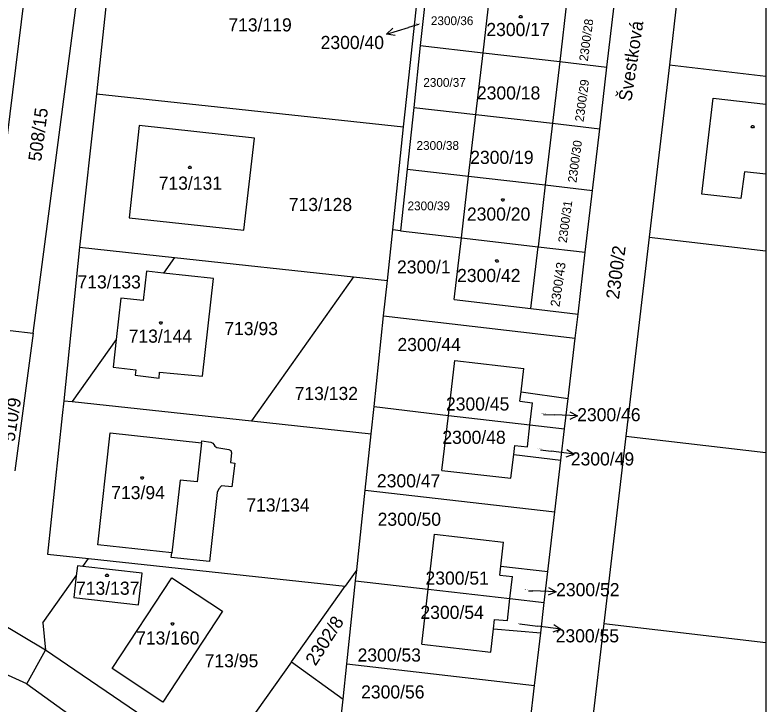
# Model space of a CAD drawing. Extents: x -639590 to -639298, y -1193269 to -1192863.
# Drawn here: x -639395.8 to -639298.4, y -1193033.8 to -1192944.4 of the extents above; entities that cross this region are included whole.
import ezdxf

# ---------------------------------------------------------------- set-up
doc = ezdxf.new("R2010")
doc.units = 0
for name, color, linetype in [('Vrstva 1', 7, 'Continuous'), ('Vrstva 2', 7, 'Continuous'), ('Vrstva 4', 7, 'Continuous'), ('Vrstva 5', 7, 'Continuous'), ('Vrstva 61', 7, 'Continuous'), ('Vrstva 7', 7, 'Continuous')]:
    doc.layers.add(name, color=color, linetype=linetype)

msp = doc.modelspace()

# ---------------------------------------------------------------- linework, layer by layer
at = {"layer": 'Vrstva 1'}
for p, q in [((-639383.03, -1192934.71), (-639385.21, -1192954.59)), ((-639393.89, -1192936.45), (-639396.82, -1192960.36)), ((-639393.41, -1192985.63), (-639387.1, -1192937.37)), ((-639345.16, -1192956.92), (-639343.26, -1192938.99)), ((-639309.56, -1192939.2), (-639310.92, -1192950.83)), ((-639342.35, -1192940.34), (-639343.21, -1192948.35)), ((-639335.07, -1192949.28), (-639334.13, -1192941.29)), ((-639324.19, -1192942.43), (-639325.13, -1192950.42)), ((-639319.01, -1192951.12), (-639318.07, -1192943.13)), ((-639343.21, -1192948.35), (-639344.07, -1192956.35)), ((-639343.21, -1192948.35), (-639335.07, -1192949.28)), ((-639336, -1192957.28), (-639335.07, -1192949.28)), ((-639335.07, -1192949.28), (-639325.13, -1192950.42)), ((-639325.13, -1192950.42), (-639326.07, -1192958.42)), ((-639325.13, -1192950.42), (-639319.01, -1192951.12)), ((-639310.92, -1192950.83), (-639313.54, -1192973.18)), ((-639310.92, -1192950.83), (-639298.391, -1192952.297)), ((-639319.94, -1192959.12), (-639319.01, -1192951.12)), ((-639385.21, -1192954.59), (-639387.39, -1192974.48)), ((-639385.21, -1192954.59), (-639345.37, -1192958.88)), ((-639306.71, -1192967.58), (-639305.24, -1192955.15)), ((-639305.24, -1192955.15), (-639298.391, -1192955.938)), ((-639344.07, -1192956.35), (-639344.93, -1192964.35)), ((-639344.07, -1192956.35), (-639336, -1192957.28)), ((-639345.37, -1192958.88), (-639345.16, -1192956.92)), ((-639336.94, -1192965.27), (-639336, -1192957.28)), ((-639336, -1192957.28), (-639326.07, -1192958.42)), ((-639379.65, -1192958.7), (-639380.96, -1192970.68)), ((-639364.71, -1192960.36), (-639379.65, -1192958.7)), ((-639326.07, -1192958.42), (-639327, -1192966.41)), ((-639326.07, -1192958.42), (-639319.94, -1192959.12)), ((-639346.65, -1192970.97), (-639345.37, -1192958.88)), ((-639320.88, -1192967.11), (-639319.94, -1192959.12)), ((-639366.1, -1192972.28), (-639364.71, -1192960.36)), ((-639344.93, -1192964.35), (-639345.79, -1192972.36)), ((-639344.93, -1192964.35), (-639336.94, -1192965.27)), ((-639337.88, -1192973.27), (-639336.94, -1192965.27)), ((-639336.94, -1192965.27), (-639327, -1192966.41)), ((-639301.16, -1192964.71), (-639301.64, -1192968.16)), ((-639298.391, -1192965.018), (-639301.16, -1192964.71)), ((-639327, -1192966.41), (-639327.94, -1192974.41)), ((-639327, -1192966.41), (-639320.88, -1192967.11)), ((-639321.82, -1192975.11), (-639320.88, -1192967.11)), ((-639301.64, -1192968.16), (-639306.71, -1192967.58)), ((-639380.96, -1192970.68), (-639366.1, -1192972.28)), ((-639346.79, -1192972.24), (-639346.65, -1192970.97)), ((-639347.48, -1192978.77), (-639346.79, -1192972.24)), ((-639345.79, -1192972.36), (-639346.79, -1192972.24)), ((-639345.79, -1192972.36), (-639337.88, -1192973.27)), ((-639338.82, -1192981.25), (-639337.88, -1192973.27)), ((-639337.88, -1192973.27), (-639327.94, -1192974.41)), ((-639313.54, -1192973.18), (-639316.56, -1192998.97)), ((-639313.54, -1192973.18), (-639298.391, -1192974.948)), ((-639328.88, -1192982.42), (-639327.94, -1192974.41)), ((-639327.94, -1192974.41), (-639321.82, -1192975.11)), ((-639387.39, -1192974.48), (-639389.43, -1192994.38)), ((-639387.39, -1192974.48), (-639375.09, -1192975.8)), ((-639322.76, -1192983.14), (-639321.82, -1192975.11)), ((-639375.09, -1192975.8), (-639376.52, -1192977.82)), ((-639375.09, -1192975.8), (-639351.85, -1192978.3)), ((-639378.73, -1192977.57), (-639379.13, -1192981.37)), ((-639376.52, -1192977.82), (-639378.73, -1192977.57)), ((-639370.03, -1192978.54), (-639376.52, -1192977.82)), ((-639351.85, -1192978.3), (-639365.1, -1192996.99)), ((-639351.85, -1192978.3), (-639347.48, -1192978.77)), ((-639371.45, -1192991.2), (-639370.03, -1192978.54)), ((-639347.97, -1192983.38), (-639347.48, -1192978.77)), ((-639382.05, -1192981.06), (-639382.64, -1192986.44)), ((-639379.13, -1192981.37), (-639382.05, -1192981.06)), ((-639338.82, -1192981.25), (-639328.88, -1192982.42)), ((-639328.88, -1192982.42), (-639322.76, -1192983.14)), ((-639323.13, -1192986.27), (-639322.76, -1192983.14)), ((-639349.21, -1192995.14), (-639347.97, -1192983.38)), ((-639347.97, -1192983.38), (-639323.13, -1192986.27)), ((-639396.4, -1192985.25), (-639393.41, -1192985.63)), ((-639393.41, -1192985.63), (-639395.79, -1193003.46)), ((-639382.64, -1192986.44), (-639388.35, -1192994.49)), ((-639382.64, -1192986.44), (-639383.03, -1192990.01)), ((-639324.04, -1192994.08), (-639323.13, -1192986.27)), ((-639383.03, -1192990.01), (-639380.1, -1192990.35)), ((-639339.57, -1192996.27), (-639338.74, -1192989.14)), ((-639338.74, -1192989.14), (-639329.8, -1192990.18)), ((-639380.1, -1192990.35), (-639380.16, -1192991.08)), ((-639377.07, -1192991.44), (-639377.01, -1192990.69)), ((-639377.01, -1192990.69), (-639371.45, -1192991.2)), ((-639330.15, -1192993.23), (-639329.8, -1192990.18)), ((-639380.16, -1192991.08), (-639377.07, -1192991.44)), ((-639330.29, -1192994.42), (-639330.15, -1192993.23)), ((-639330.15, -1192993.23), (-639324.04, -1192994.08)), ((-639389.43, -1192994.38), (-639389.63, -1192996.3)), ((-639389.43, -1192994.38), (-639388.35, -1192994.49)), ((-639388.35, -1192994.49), (-639365.1, -1192996.99)), ((-639330.29, -1192994.42), (-639328.66, -1192994.65)), ((-639328.99, -1192997.5), (-639328.66, -1192994.65)), ((-639324.5, -1192998.02), (-639324.04, -1192994.08)), ((-639349.58, -1192998.66), (-639349.21, -1192995.14)), ((-639349.21, -1192995.14), (-639339.57, -1192996.27)), ((-639389.63, -1192996.3), (-639391.56, -1193014.27)), ((-639340.4, -1193003.4), (-639339.57, -1192996.27)), ((-639339.57, -1192996.27), (-639328.99, -1192997.5)), ((-639365.1, -1192996.99), (-639349.58, -1192998.66)), ((-639329.33, -1193000.35), (-639328.99, -1192997.5)), ((-639328.99, -1192997.5), (-639324.5, -1192998.02)), ((-639385, -1193013.06), (-639383.4, -1192998.52)), ((-639383.4, -1192998.52), (-639371.56, -1192999.81)), ((-639350.36, -1193005.95), (-639349.58, -1192998.66)), ((-639324.98, -1193002.06), (-639324.5, -1192998.02)), ((-639371.56, -1192999.81), (-639371.54, -1192999.58)), ((-639371.54, -1192999.58), (-639370.37, -1192999.75)), ((-639316.56, -1192998.97), (-639319.4, -1193023.24)), ((-639316.56, -1192998.97), (-639298.391, -1193001.096)), ((-639370.37, -1192999.75), (-639370.12, -1192999.88)), ((-639370.12, -1192999.88), (-639369.99, -1193000.06)), ((-639369.99, -1193000.06), (-639369.86, -1193000.28)), ((-639369.86, -1193000.28), (-639369.57, -1193000.43)), ((-639369.57, -1193000.43), (-639368.03, -1193000.71)), ((-639368.03, -1193000.71), (-639367.76, -1193000.83)), ((-639331.1, -1193001.35), (-639330.97, -1193000.16)), ((-639330.97, -1193000.16), (-639329.33, -1193000.35)), ((-639367.71, -1193001.13), (-639367.82, -1193002.4)), ((-639367.76, -1193000.83), (-639367.71, -1193001.13)), ((-639331.46, -1193004.43), (-639331.1, -1193001.35)), ((-639331.1, -1193001.35), (-639324.98, -1193002.06)), ((-639367.82, -1193002.4), (-639367.25, -1193002.47)), ((-639367.25, -1193002.47), (-639367.65, -1193005.55)), ((-639325.76, -1193008.79), (-639324.98, -1193002.06)), ((-639340.4, -1193003.4), (-639331.46, -1193004.43)), ((-639368.97, -1193005.42), (-639369.34, -1193005.78)), ((-639367.65, -1193005.55), (-639368.97, -1193005.42)), ((-639369.53, -1193006.28), (-639370.56, -1193015.2)), ((-639369.34, -1193005.78), (-639369.53, -1193006.28)), ((-639351.45, -1193016.27), (-639350.36, -1193005.95)), ((-639350.36, -1193005.95), (-639325.76, -1193008.79)), ((-639326.66, -1193016.49), (-639325.76, -1193008.79)), ((-639342.18, -1193018.8), (-639341.36, -1193011.67)), ((-639341.36, -1193011.67), (-639332.41, -1193012.71)), ((-639375.43, -1193014.08), (-639385, -1193013.06)), ((-639332.76, -1193015.8), (-639332.41, -1193012.71)), ((-639391.56, -1193014.27), (-639386.24, -1193014.84)), ((-639375.49, -1193014.71), (-639375.43, -1193014.08)), ((-639386.95, -1193015.84), (-639386.24, -1193014.84)), ((-639386.24, -1193014.84), (-639352.97, -1193018.41)), ((-639370.56, -1193015.2), (-639375.49, -1193014.71)), ((-639387.67, -1193015.75), (-639387.82, -1193017.06)), ((-639386.95, -1193015.84), (-639387.67, -1193015.75)), ((-639379.28, -1193016.74), (-639386.95, -1193015.84)), ((-639351.45, -1193016.27), (-639352.97, -1193018.41)), ((-639351.6, -1193017.71), (-639351.45, -1193016.27)), ((-639332.9, -1193016.99), (-639332.76, -1193015.8)), ((-639332.76, -1193015.8), (-639326.66, -1193016.49)), ((-639392.15, -1193023.17), (-639387.82, -1193017.06)), ((-639387.82, -1193017.06), (-639388.13, -1193019.87)), ((-639379.76, -1193020.83), (-639379.28, -1193016.74)), ((-639332.9, -1193016.99), (-639331.26, -1193017.17)), ((-639331.59, -1193020.02), (-639331.26, -1193017.17)), ((-639327.14, -1193020.54), (-639326.66, -1193016.49)), ((-639383.17, -1193029.06), (-639375.42, -1193017.33)), ((-639375.42, -1193017.33), (-639368.86, -1193021.65)), ((-639352.74, -1193028.49), (-639351.6, -1193017.71)), ((-639351.6, -1193017.71), (-639342.18, -1193018.8)), ((-639359.93, -1193028.23), (-639352.97, -1193018.41)), ((-639342.99, -1193025.93), (-639342.18, -1193018.8)), ((-639342.18, -1193018.8), (-639331.59, -1193020.02)), ((-639388.13, -1193019.87), (-639379.76, -1193020.83)), ((-639331.92, -1193022.87), (-639331.59, -1193020.02)), ((-639331.59, -1193020.02), (-639327.14, -1193020.54)), ((-639391.81, -1193026.72), (-639401.32, -1193021.01)), ((-639327.6, -1193024.45), (-639327.14, -1193020.54)), ((-639368.86, -1193021.65), (-639376.61, -1193033.42)), ((-639333.72, -1193023.92), (-639333.58, -1193022.73)), ((-639333.58, -1193022.73), (-639331.92, -1193022.87)), ((-639392.15, -1193023.17), (-639391.81, -1193026.72)), ((-639334.07, -1193026.98), (-639333.72, -1193023.92)), ((-639333.72, -1193023.92), (-639327.6, -1193024.45)), ((-639319.4, -1193023.24), (-639322.6, -1193050.55)), ((-639319.4, -1193023.24), (-639298.391, -1193025.698)), ((-639328.4, -1193031.29), (-639327.6, -1193024.45)), ((-639342.99, -1193025.93), (-639334.07, -1193026.98)), ((-639394.21, -1193031.06), (-639391.81, -1193026.72)), ((-639388.01, -1193029.3), (-639391.81, -1193026.72)), ((-639359.93, -1193028.23), (-639369.56, -1193041.81)), ((-639359.93, -1193028.23), (-639353.23, -1193033.04)), ((-639353.23, -1193033.04), (-639352.74, -1193028.49)), ((-639352.74, -1193028.49), (-639328.4, -1193031.29)), ((-639394.21, -1193031.06), (-639398.1, -1193029.3)), ((-639369.56, -1193041.81), (-639388.01, -1193029.3)), ((-639376.61, -1193033.42), (-639383.17, -1193029.06)), ((-639394.21, -1193031.06), (-639377.41, -1193043.16)), ((-639329.3, -1193039.04), (-639328.4, -1193031.29)), ((-639353.99, -1193040.25), (-639353.23, -1193033.04))]:
    msp.add_line(p, q, dxfattribs=at)
at = {"layer": 'Vrstva 4'}
for p, q in [((-639371.56, -1192999.81), (-639372.13, -1193004.88)), ((-639374.33, -1193004.66), (-639375.43, -1193014.08)), ((-639372.13, -1193004.88), (-639374.33, -1193004.66))]:
    msp.add_line(p, q, dxfattribs=at)
at = {"layer": 'Vrstva 5'}
for points in [[(-639330.11, -1192944.46), (-639330.02, -1192944.61), (-639330.11, -1192944.76), (-639330.29, -1192944.76), (-639330.38, -1192944.61), (-639330.29, -1192944.46)], [(-639300.03, -1192958.72), (-639299.94, -1192958.87), (-639300.03, -1192959.02), (-639300.21, -1192959.02), (-639300.3, -1192958.87), (-639300.21, -1192958.72)], [(-639372.99, -1192963.99), (-639372.9, -1192964.14), (-639372.99, -1192964.29), (-639373.17, -1192964.29), (-639373.26, -1192964.14), (-639373.17, -1192963.99)], [(-639332.41, -1192968.2), (-639332.32, -1192968.35), (-639332.41, -1192968.5), (-639332.59, -1192968.5), (-639332.68, -1192968.35), (-639332.59, -1192968.2)], [(-639333.18, -1192976.11), (-639333.09, -1192976.26), (-639333.18, -1192976.41), (-639333.36, -1192976.41), (-639333.45, -1192976.26), (-639333.36, -1192976.11)], [(-639376.77, -1192984.13), (-639376.68, -1192984.28), (-639376.77, -1192984.43), (-639376.95, -1192984.43), (-639377.04, -1192984.28), (-639376.95, -1192984.13)], [(-639379.19, -1193004.22), (-639379.1, -1193004.37), (-639379.19, -1193004.52), (-639379.37, -1193004.52), (-639379.46, -1193004.37), (-639379.37, -1193004.22)], [(-639383.74, -1193016.87), (-639383.65, -1193017.02), (-639383.74, -1193017.17), (-639383.92, -1193017.17), (-639384.01, -1193017.02), (-639383.92, -1193016.87)], [(-639375.26, -1193023.15), (-639375.17, -1193023.3), (-639375.26, -1193023.45), (-639375.44, -1193023.45), (-639375.53, -1193023.3), (-639375.44, -1193023.15)]]:
    msp.add_lwpolyline(points, close=True, dxfattribs=at)
at = {"layer": 'Vrstva 61'}
msp.add_lwpolyline([(-639298.391, -1192863.27), (-639298.391, -1193268.77)], dxfattribs=at)
at = {"layer": 'Vrstva 7'}
for p, q in [((-639347.588, -1192946.869), (-639344.72, -1192945.99)), ((-639343.46, -1192945.61), (-639344.72, -1192945.99)), ((-639327.22, -1192996.16), (-639325.82, -1192996.22)), ((-639322.822, -1192996.335), (-639325.82, -1192996.22)), ((-639327.64, -1193000.73), (-639326.25, -1193000.91)), ((-639323.276, -1193001.306), (-639326.25, -1193000.91)), ((-639329.17, -1193019), (-639328.6, -1193019.02)), ((-639325.602, -1193019.126), (-639328.6, -1193019.02)), ((-639330.34, -1193023.28), (-639327.95, -1193023.59)), ((-639324.976, -1193023.983), (-639327.95, -1193023.59))]:
    msp.add_line(p, q, dxfattribs=at)
for points in [[(-639346.486, -1192947.054), (-639347.588, -1192946.869), (-639346.779, -1192946.098)], [(-639323.802, -1192995.797), (-639322.822, -1192996.335), (-639323.841, -1192996.796)], [(-639324.201, -1193000.678), (-639323.276, -1193001.306), (-639324.334, -1193001.67)], [(-639326.584, -1193018.591), (-639325.602, -1193019.126), (-639326.619, -1193019.59)], [(-639325.902, -1193023.356), (-639324.976, -1193023.983), (-639326.033, -1193024.348)]]:
    msp.add_lwpolyline(points, dxfattribs=at)

# ---------------------------------------------------------------- texts
at = {"layer": 'Vrstva 2'}
for s, height, p in [('713/119', 1.7, (-639368.095, -1192946.51)), ('2300/36', 1.14, (-639341.839, -1192945.69)), ('2300/40', 0.1, (-639343.757, -1192945.61)), ('2300/17', 1.7, (-639334.648, -1192947.11)), ('2300/37', 1.14, (-639342.822, -1192953.69)), ('2300/18', 1.7, (-639335.868, -1192955.33)), ('2300/38', 1.14, (-639343.702, -1192961.86)), ('2300/19', 1.7, (-639336.738, -1192963.68)), ('713/131', 1.7, (-639377.132, -1192967.02)), ('713/128', 1.7, (-639360.266, -1192969.79)), ('2300/39', 1.14, (-639344.869, -1192969.69)), ('2300/20', 1.7, (-639337.166, -1192971.03)), ('2300/1', 1.7, (-639346.233, -1192977.88)), ('2300/42', 1.7, (-639338.44, -1192978.99)), ('713/133', 1.7, (-639387.657, -1192979.82)), ('713/93', 1.7, (-639368.618, -1192985.87)), ('713/144', 1.7, (-639381.023, -1192986.85)), ('2300/44', 1.7, (-639346.173, -1192987.94)), ('713/132', 1.7, (-639359.503, -1192994.28)), ('2300/45', 1.7, (-639339.883, -1192995.64)), ('2300/46', 0.1, (-639327.496, -1192996.08)), ('2300/48', 1.7, (-639340.356, -1192999.96)), ('2300/49', 0.1, (-639327.996, -1193000.65)), ('2300/47', 1.7, (-639348.833, -1193005.6)), ('713/94', 1.7, (-639383.281, -1193007.13)), ('713/134', 1.7, (-639365.77, -1193008.73)), ('2300/50', 1.7, (-639348.743, -1193010.58)), ('2300/51', 1.7, (-639342.535, -1193018.21)), ('713/137', 1.7, (-639387.849, -1193019.52)), ('2300/52', 0.1, (-639329.746, -1193018.92)), ('2300/54', 1.7, (-639343.193, -1193022.65)), ('2300/55', 0.1, (-639330.656, -1193023.32)), ('713/160', 1.7, (-639380.059, -1193025.97)), ('2300/53', 1.7, (-639351.343, -1193028.18)), ('713/95', 1.7, (-639371.168, -1193028.92)), ('2300/56', 1.7, (-639350.883, -1193032.96))]:
    msp.add_text(s, height=height, dxfattribs=at).set_placement(p)
for s, height, rotation, p in [('2300/28', 1.14, 82.33404, (-639321.498, -1192950.423)), ('2300/29', 1.14, 82.33404, (-639322.046, -1192958.279)), ('508/15', 1.7, 82.50592, (-639392.371, -1192963.418)), ('2300/30', 1.14, 82.33404, (-639322.97, -1192966.166)), ('2300/31', 1.14, 82.33404, (-639324.226, -1192973.967)), ('2300/2', 1.7, 82.62051, (-639317.46, -1192981.285)), ('2300/43', 1.2, 81.87567, (-639325.166, -1192982.254)), ('510/9', 1.7, 81.13083, (-639395.827, -1192999.741)), ('2302/8', 1.7, 57.23848, (-639356.802, -1193028.84))]:
    msp.add_text(s, height=height, rotation=rotation, dxfattribs=at).set_placement(p)
at = {"layer": 'Vrstva 7'}
msp.add_text('Švestková', height=1.7, rotation=81.36001, dxfattribs=at).set_placement((-639315.844, -1192955.645))
for s, p in [('2300/40', (-639356.133, -1192948.79)), ('2300/46', (-639322.866, -1192997.03)), ('2300/49', (-639323.696, -1193002.76)), ('2300/52', (-639325.596, -1193019.71)), ('2300/55', (-639325.66, -1193025.69))]:
    msp.add_text(s, height=1.7, dxfattribs=at).set_placement(p)

doc.saveas('drawing.dxf')
